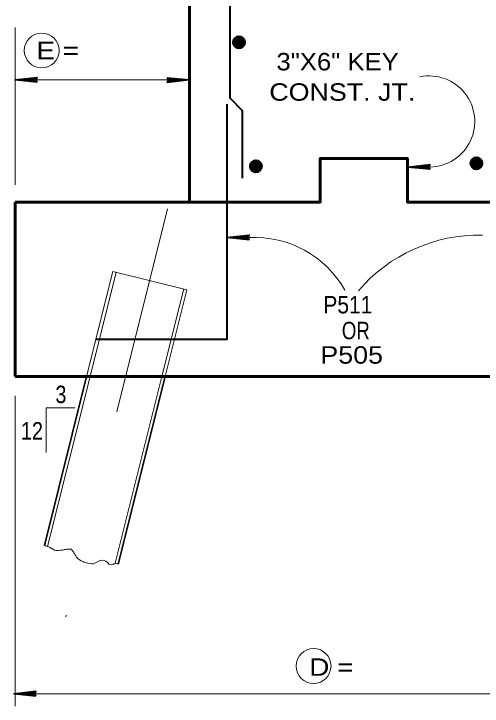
# Model space of a CAD drawing. Extents: x 3.64 to 6.84, y -0.8 to 1.19.
# Drawn here: x 5.0183 to 5.2422, y -0.2994 to 0.0313 of the extents above; entities that cross this region are included whole.
import ezdxf
from ezdxf.enums import TextEntityAlignment as Align

# ---------------------------------------------------------------- set-up
doc = ezdxf.new("R2010")
doc.units = 0
doc.header["$LTSCALE"] = 0.0033
doc.linetypes.add('DOT_DASHED', pattern=[7.7, 5, -1.2, 0.3, -1.2])
doc.linetypes.add('MEDIUM_DASHED', pattern=[4.5, 3, -1.5])
doc.layers.add('1', color=7, linetype='Continuous', lineweight=40)
doc.layers.add('5', color=7, linetype='MEDIUM_DASHED', lineweight=13)

msp = doc.modelspace()

# ---------------------------------------------------------------- linework, layer by layer
at = {"layer": '1', "lineweight": 13}
for p, q in [((5.018917, -0.050417), (5.018917, 0.024667)), ((5.018917, -0.000333), (5.100333, -0.000333)), ((5.018917, -0.151167), (5.018917, -0.299417)), ((5.033833, -0.156917), (5.033833, -0.17825)), ((5.033833, -0.156917), (5.0475, -0.156917)), ((5.018417, -0.2935), (5.35175, -0.2935))]:
    msp.add_line(p, q, dxfattribs=at)
at = {"layer": '1'}
for p, q in [((5.12825, 0.018917), (5.127, 0.020083)), ((5.12375, 0.017), (5.127667, 0.01625)), ((5.12375, 0.016833), (5.127583, 0.016083)), ((5.12375, 0.016583), (5.127583, 0.015917)), ((5.123833, 0.01925), (5.128417, 0.017083)), ((5.123833, 0.017417), (5.12775, 0.016667)), ((5.123917, 0.017833), (5.12775, 0.017083)), ((5.123917, 0.017667), (5.12775, 0.016917)), ((5.124, 0.01825), (5.127833, 0.017583)), ((5.124, 0.018083), (5.127833, 0.017333)), ((5.124083, 0.018833), (5.128, 0.018083)), ((5.124083, 0.018667), (5.128, 0.017917)), ((5.124083, 0.018417), (5.127917, 0.017667)), ((5.124167, 0.01925), (5.128083, 0.018583)), ((5.124167, 0.019083), (5.128083, 0.018333)), ((5.12425, 0.019583), (5.128083, 0.018917)), ((5.126167, 0.01875), (5.1275, 0.01975)), ((5.123667, 0.0165), (5.1275, 0.01575)), ((5.123667, 0.016333), (5.1275, 0.015583)), ((5.128, 0.016083), (5.12425, 0.015667)), ((5.132333, -0.039667), (5.136167, -0.040333)), ((5.13425, -0.0405), (5.135583, -0.0395)), ((5.136333, -0.040333), (5.135083, -0.039167)), ((5.237333, -0.038583), (5.241917, -0.04075)), ((5.2375, -0.039583), (5.241333, -0.04025)), ((5.237583, -0.039), (5.2415, -0.03975)), ((5.237583, -0.039167), (5.2415, -0.039917)), ((5.237583, -0.039417), (5.241417, -0.040167)), ((5.237667, -0.038583), (5.241583, -0.03925)), ((5.237667, -0.03875), (5.241583, -0.0395)), ((5.23775, -0.03825), (5.241583, -0.038917)), ((5.239667, -0.039083), (5.241, -0.038083)), ((5.24175, -0.038917), (5.2405, -0.03775)), ((5.13175, -0.04275), (5.135583, -0.0435)), ((5.13175, -0.042917), (5.135583, -0.043667)), ((5.131833, -0.04225), (5.13575, -0.043)), ((5.131833, -0.042417), (5.135667, -0.043167)), ((5.131833, -0.042667), (5.135667, -0.043333)), ((5.131917, -0.04), (5.1365, -0.042167)), ((5.131917, -0.041833), (5.135833, -0.042583)), ((5.132, -0.041417), (5.135833, -0.042167)), ((5.132, -0.041583), (5.135833, -0.042333)), ((5.132083, -0.041), (5.135917, -0.041667)), ((5.132083, -0.041167), (5.135917, -0.041917)), ((5.132167, -0.040417), (5.136083, -0.041167)), ((5.132167, -0.040583), (5.136083, -0.041333)), ((5.132167, -0.040833), (5.136, -0.041583)), ((5.13225, -0.04), (5.136167, -0.040667)), ((5.13225, -0.040167), (5.136167, -0.040917)), ((5.237167, -0.041333), (5.241, -0.042083)), ((5.237167, -0.0415), (5.241, -0.04225)), ((5.23725, -0.040833), (5.241167, -0.041583)), ((5.23725, -0.041), (5.241083, -0.04175)), ((5.23725, -0.04125), (5.241083, -0.041917)), ((5.237333, -0.040417), (5.24125, -0.041167)), ((5.237417, -0.04), (5.24125, -0.04075)), ((5.237417, -0.040167), (5.24125, -0.040917)), ((5.2375, -0.03975), (5.241333, -0.0405)), ((5.2415, -0.04175), (5.23775, -0.042167)), ((5.136083, -0.043167), (5.132333, -0.043583))]:
    msp.add_line(p, q, dxfattribs=at)
at = {"layer": '1', "lineweight": 60}
for p, q in [((5.128417, 0.017083), (5.123667, 0.016333)), ((5.124083, 0.01925), (5.123917, 0.016333)), ((5.124333, 0.01925), (5.124083, 0.016333)), ((5.1245, 0.01925), (5.124333, 0.01625)), ((5.124667, 0.01925), (5.124417, 0.01625)), ((5.124833, 0.01925), (5.124667, 0.01625)), ((5.125083, 0.01925), (5.124917, 0.01625)), ((5.125333, 0.01925), (5.125083, 0.01625)), ((5.125417, 0.019167), (5.12525, 0.01625)), ((5.125583, 0.019167), (5.125417, 0.01625)), ((5.12575, 0.019167), (5.125583, 0.01625)), ((5.126, 0.019167), (5.12575, 0.01625)), ((5.126167, 0.019167), (5.126, 0.01625)), ((5.126417, 0.019083), (5.126167, 0.016167)), ((5.126667, 0.019083), (5.126417, 0.016167)), ((5.126833, 0.019083), (5.126667, 0.016167)), ((5.126917, 0.019083), (5.12675, 0.016167)), ((5.127083, 0.019083), (5.126917, 0.016167)), ((5.127167, 0.019083), (5.127, 0.016167)), ((5.127417, 0.019), (5.127167, 0.016083)), ((5.127583, 0.019), (5.127417, 0.016083)), ((5.12775, 0.019), (5.1275, 0.016083)), ((5.127917, 0.019), (5.12775, 0.016083)), ((5.128167, 0.019), (5.128, 0.016083)), ((5.128417, 0.017083), (5.12825, 0.018917)), ((5.237583, -0.038583), (5.237417, -0.0415)), ((5.237833, -0.038583), (5.237583, -0.0415)), ((5.238, -0.038583), (5.237833, -0.041583)), ((5.238167, -0.038583), (5.237917, -0.041583)), ((5.238333, -0.038583), (5.238167, -0.041583)), ((5.238583, -0.038583), (5.238417, -0.041583)), ((5.238833, -0.038583), (5.238583, -0.041583)), ((5.238917, -0.038667), (5.23875, -0.041583)), ((5.239083, -0.038667), (5.238917, -0.041583)), ((5.23925, -0.038667), (5.239083, -0.041583)), ((5.2395, -0.038667), (5.23925, -0.041583)), ((5.239667, -0.038667), (5.2395, -0.041583)), ((5.239917, -0.03875), (5.239667, -0.041667)), ((5.240167, -0.03875), (5.239917, -0.041667)), ((5.240333, -0.03875), (5.240167, -0.041667)), ((5.240417, -0.03875), (5.24025, -0.041667)), ((5.240583, -0.03875), (5.240417, -0.041667)), ((5.240667, -0.03875), (5.2405, -0.041667)), ((5.240917, -0.038833), (5.240667, -0.04175)), ((5.241083, -0.038833), (5.240917, -0.04175)), ((5.24125, -0.038833), (5.241, -0.04175)), ((5.241417, -0.038833), (5.24125, -0.04175)), ((5.241667, -0.038833), (5.2415, -0.04175)), ((5.241917, -0.04075), (5.24175, -0.038917)), ((5.1365, -0.042167), (5.13175, -0.042917)), ((5.132167, -0.04), (5.132, -0.042917)), ((5.132417, -0.04), (5.132167, -0.042917)), ((5.132583, -0.04), (5.132417, -0.043)), ((5.13275, -0.04), (5.1325, -0.043)), ((5.132917, -0.04), (5.13275, -0.043)), ((5.133167, -0.04), (5.133, -0.043)), ((5.133417, -0.04), (5.133167, -0.043)), ((5.1335, -0.040083), (5.133333, -0.043)), ((5.133667, -0.040083), (5.1335, -0.043)), ((5.133833, -0.040083), (5.133667, -0.043)), ((5.134083, -0.040083), (5.133833, -0.043)), ((5.13425, -0.040083), (5.134083, -0.043)), ((5.1345, -0.040167), (5.13425, -0.043083)), ((5.13475, -0.040167), (5.1345, -0.043083)), ((5.134917, -0.040167), (5.13475, -0.043083)), ((5.135, -0.040167), (5.134833, -0.043083)), ((5.135167, -0.040167), (5.135, -0.043083)), ((5.13525, -0.040167), (5.135083, -0.043083)), ((5.1355, -0.04025), (5.13525, -0.043167)), ((5.135667, -0.04025), (5.1355, -0.043167)), ((5.135833, -0.04025), (5.135583, -0.043167)), ((5.136, -0.04025), (5.135833, -0.043167)), ((5.13625, -0.04025), (5.136083, -0.043167)), ((5.1365, -0.042167), (5.136333, -0.040333)), ((5.241917, -0.04075), (5.237167, -0.0415)), ((5.018917, -0.142), (5.018917, -0.058667)), ((5.35225, -0.142), (5.018917, -0.142))]:
    msp.add_line(p, q, dxfattribs=at)
at = {"layer": '1', "lineweight": 35}
for p, q in [((5.02925, 0.00075), (5.021917, -0.000083)), ((5.02925, 0.000583), (5.021917, -0.000167)), ((5.02925, 0.0005), (5.021917, -0.000333)), ((5.029333, 0.000333), (5.022, -0.000417)), ((5.091833, 0.000667), (5.099667, -0.00025)), ((5.091833, 0.000667), (5.099667, -0.00025)), ((5.091833, 0.000583), (5.099667, -0.00025)), ((5.091833, 0.0005), (5.099667, -0.000333)), ((5.091833, 0.0005), (5.099667, -0.0005)), ((5.0295, -0.000333), (5.018917, -0.000333)), ((5.02925, -0.001167), (5.021417, -0.000167)), ((5.02925, -0.001167), (5.021417, -0.000333)), ((5.02925, -0.001333), (5.021417, -0.000417)), ((5.02925, -0.001333), (5.021417, -0.000417)), ((5.02925, -0.00125), (5.021417, -0.000417)), ((5.091583, -0.000333), (5.102167, -0.000333)), ((5.09175, -0.001), (5.099083, -0.00025)), ((5.091833, -0.001167), (5.099167, -0.000333)), ((5.091833, -0.00125), (5.099167, -0.0005)), ((5.091833, -0.001417), (5.099167, -0.000583)), ((5.21725, -0.041917), (5.206667, -0.041917)), ((5.217, -0.04275), (5.209167, -0.04175)), ((5.217, -0.04275), (5.209167, -0.041917)), ((5.217, -0.042917), (5.209167, -0.042)), ((5.217, -0.042917), (5.209167, -0.042)), ((5.217, -0.042833), (5.209167, -0.042)), ((5.217, -0.040833), (5.209667, -0.041667)), ((5.217, -0.041), (5.209667, -0.04175)), ((5.217, -0.041083), (5.209667, -0.041917)), ((5.217083, -0.04125), (5.20975, -0.042)), ((5.130833, -0.075583), (5.12025, -0.075583)), ((5.130583, -0.076417), (5.12275, -0.075417)), ((5.130583, -0.076417), (5.12275, -0.075583)), ((5.130583, -0.076583), (5.12275, -0.075667)), ((5.130583, -0.076583), (5.12275, -0.075667)), ((5.130583, -0.0765), (5.12275, -0.075667)), ((5.130583, -0.0745), (5.12325, -0.075333)), ((5.130583, -0.074667), (5.12325, -0.075417)), ((5.130583, -0.07475), (5.12325, -0.075583)), ((5.130667, -0.074917), (5.123333, -0.075667)), ((5.028917, -0.2935), (5.018333, -0.2935)), ((5.028667, -0.294333), (5.020833, -0.293333)), ((5.028667, -0.294333), (5.020833, -0.2935)), ((5.028667, -0.2945), (5.020833, -0.293583)), ((5.028667, -0.2945), (5.020833, -0.293583)), ((5.028667, -0.294417), (5.020833, -0.293583)), ((5.028667, -0.292417), (5.021333, -0.29325)), ((5.028667, -0.292583), (5.021333, -0.293333)), ((5.028667, -0.292667), (5.021333, -0.2935)), ((5.02875, -0.292833), (5.021417, -0.293583))]:
    msp.add_line(p, q, dxfattribs=at)
at = {"layer": '1', "lineweight": 60}
for points in [[(5.018917, -0.058667), (5.10225, -0.058667), (5.10225, 0.274667), (5.268917, 0.274667), (5.268917, -0.058667), (5.35225, -0.058667)], [(5.1275, 0.015583), (5.1275, 0.01975), (5.125833, 0.015083), (5.126333, 0.02025), (5.12425, 0.015667), (5.125, 0.020167), (5.126583, 0.015167), (5.123417, 0.0185), (5.12825, 0.018917), (5.125, 0.01525), (5.127, 0.020083), (5.123833, 0.01925), (5.123667, 0.016333)], [(5.12425, 0.015667), (5.12575, 0.017917), (5.123583, 0.018833), (5.125583, 0.02025), (5.12575, 0.018), (5.127417, 0.015667), (5.123417, 0.018), (5.126167, 0.01875)], [(5.127, 0.020083), (5.12575, 0.017917), (5.128, 0.016083)], [(5.12325, 0.017583), (5.128417, 0.01825), (5.123833, 0.01925)], [(5.10225, -0.058667), (5.16475, -0.058667), (5.16475, -0.037833), (5.206417, -0.037833), (5.206417, -0.058667), (5.268917, -0.058667)], [(5.135583, -0.043667), (5.135583, -0.0395), (5.133917, -0.044167), (5.134417, -0.039), (5.132333, -0.043583), (5.133083, -0.039083), (5.134667, -0.044083), (5.1315, -0.04075), (5.136333, -0.040333), (5.133083, -0.044), (5.135083, -0.039167), (5.131917, -0.04), (5.13175, -0.042917)], [(5.132333, -0.043583), (5.133833, -0.041333), (5.131667, -0.040417), (5.133667, -0.039), (5.133833, -0.04125), (5.1355, -0.043583), (5.1315, -0.04125), (5.13425, -0.0405)], [(5.135083, -0.039167), (5.133833, -0.041333), (5.136083, -0.043167)], [(5.23675, -0.04025), (5.241917, -0.039583), (5.237333, -0.038583)], [(5.241, -0.04225), (5.241, -0.038083), (5.239333, -0.04275), (5.239833, -0.037583), (5.23775, -0.042167), (5.2385, -0.037667), (5.240083, -0.042667), (5.236917, -0.039333), (5.24175, -0.038917), (5.2385, -0.042583), (5.2405, -0.03775), (5.237333, -0.038583), (5.237167, -0.0415)], [(5.23775, -0.042167), (5.23925, -0.039917), (5.237083, -0.039), (5.239083, -0.037583), (5.23925, -0.039833), (5.240917, -0.042167), (5.236917, -0.039833), (5.239667, -0.039083)], [(5.2405, -0.03775), (5.23925, -0.039917), (5.2415, -0.04175)], [(5.131333, -0.041667), (5.1365, -0.041), (5.131917, -0.04)]]:
    msp.add_lwpolyline(points, dxfattribs=at)
at = {"layer": '1'}
for points in [[(5.127417, 0.254), (5.127417, 0.205333), (5.1215, 0.199417), (5.1215, -0.008917), (5.127417, -0.014833), (5.127417, -0.04725)], [(5.123667, 0.016333), (5.12575, 0.015083), (5.1275, 0.015583), (5.128417, 0.017083)], [(5.057833, -0.124083), (5.120333, -0.124083), (5.120333, -0.011917)], [(5.13175, -0.042917), (5.133833, -0.044167), (5.135583, -0.043667), (5.1365, -0.042167)], [(5.237167, -0.0415), (5.23925, -0.04275), (5.241, -0.04225), (5.241917, -0.04075)]]:
    msp.add_lwpolyline(points, dxfattribs=at)
at = {"layer": '1', "lineweight": 35}
for points in [[(5.0295, -0.001417), (5.018917, -0.000333), (5.0295, 0.000833), (5.028917, -0.000333)], [(5.02875, -0.000417), (5.024083, -0.0005), (5.024083, -0.000417), (5.025, -0.000417), (5.02875, -0.0005), (5.02575, -0.000583), (5.028917, -0.000667), (5.026667, -0.00075), (5.028917, -0.000833), (5.025417, -0.000583), (5.02075, -0.000417), (5.021667, -0.000167), (5.020417, -0.000167), (5.02875, -0.000167), (5.026333, 0), (5.028917, 0), (5.023583, -0.000417), (5.028917, 0.00025)], [(5.091583, 0.00075), (5.102167, -0.000333), (5.091583, -0.0015), (5.092167, -0.000333)], [(5.092333, -0.00025), (5.097, -0.000167), (5.097, -0.00025), (5.096083, -0.00025), (5.092333, -0.000167), (5.095333, -0.000083), (5.092167, 0), (5.094417, 0.000083), (5.092167, 0.000167), (5.095667, -0.000083), (5.100333, -0.00025), (5.099417, -0.0005), (5.100667, -0.0005), (5.092333, -0.0005), (5.09475, -0.000667), (5.092167, -0.000667), (5.0975, -0.00025), (5.092167, -0.000917)], [(5.21725, -0.043), (5.206667, -0.041917), (5.21725, -0.04075), (5.216667, -0.041917)], [(5.2165, -0.042), (5.211833, -0.042083), (5.211833, -0.042), (5.21275, -0.042), (5.2165, -0.042083), (5.2135, -0.042167), (5.216667, -0.04225), (5.214417, -0.042333), (5.216667, -0.042417), (5.213167, -0.042167), (5.2085, -0.042), (5.209417, -0.04175), (5.208167, -0.04175), (5.2165, -0.04175), (5.214083, -0.041583), (5.216667, -0.041583), (5.211333, -0.042), (5.216667, -0.041333)], [(5.130833, -0.076667), (5.12025, -0.075583), (5.130833, -0.074417), (5.13025, -0.075583)], [(5.130083, -0.075667), (5.125417, -0.07575), (5.125417, -0.075667), (5.126333, -0.075667), (5.130083, -0.07575), (5.127083, -0.075833), (5.13025, -0.075917), (5.128, -0.076), (5.13025, -0.076083), (5.12675, -0.075833), (5.122083, -0.075667), (5.123, -0.075417), (5.12175, -0.075417), (5.130083, -0.075417), (5.127667, -0.07525), (5.13025, -0.07525), (5.124917, -0.075667), (5.13025, -0.075)], [(5.028917, -0.294583), (5.018333, -0.2935), (5.028917, -0.292333), (5.028333, -0.2935)], [(5.028167, -0.293583), (5.0235, -0.293667), (5.0235, -0.293583), (5.024417, -0.293583), (5.028167, -0.293667), (5.025167, -0.29375), (5.028333, -0.293833), (5.026083, -0.293917), (5.028333, -0.294), (5.024833, -0.29375), (5.020167, -0.293583), (5.021083, -0.293333), (5.019833, -0.293333), (5.028167, -0.293333), (5.02575, -0.293167), (5.028333, -0.293167), (5.023, -0.293583), (5.028333, -0.292917)]]:
    msp.add_lwpolyline(points, close=True, dxfattribs=at)
for points in [[(5.02875, -0.000417), (5.029167, -0.001167), (5.028917, -0.000917), (5.02875, -0.000583), (5.0285, -0.000667), (5.028667, -0.001), (5.028833, -0.00025), (5.029, 0.00025), (5.02925, 0.000667)], [(5.092333, -0.00025), (5.091917, 0.0005), (5.092167, 0.00025), (5.092333, -0.000083), (5.092583, 0), (5.092417, 0.000333), (5.09225, -0.000417), (5.092083, -0.000917), (5.091833, -0.001333)], [(5.2165, -0.042), (5.216917, -0.04275), (5.216667, -0.0425), (5.2165, -0.042167), (5.21625, -0.04225), (5.216417, -0.042583), (5.216583, -0.041833), (5.21675, -0.041333), (5.217, -0.040917)], [(5.130083, -0.075667), (5.1305, -0.076417), (5.13025, -0.076167), (5.130083, -0.075833), (5.129833, -0.075917), (5.13, -0.07625), (5.130167, -0.0755), (5.130333, -0.075), (5.130583, -0.074583)], [(5.028167, -0.293583), (5.028583, -0.294333), (5.028333, -0.294083), (5.028167, -0.29375), (5.027917, -0.293833), (5.028083, -0.294167), (5.02825, -0.293417), (5.028417, -0.292917), (5.028667, -0.2925)]]:
    msp.add_lwpolyline(points, dxfattribs=at)
at = {"layer": '1', "lineweight": 13}
for centre in [(5.031667, 0.01375), (5.161583, -0.28025)]:
    msp.add_circle(centre, 0.008333, dxfattribs=at)
at = {"layer": '1', "lineweight": 60}
for centre in [(5.125917, 0.017683), (5.134, -0.041567), (5.239417, -0.04015)]:
    msp.add_circle(centre, 0.00264, dxfattribs=at)
at = {"layer": '1', "lineweight": 13}
for centre, radius, start, end in [((5.216829, -0.020151), 0.02177, 271.10937, 101.69263), ((5.133284, -0.125296), 0.049773, 29.5481, 92.8223), ((5.240845, -0.150605), 0.076202, 88.94317, 139.38493)]:
    msp.add_arc(centre, radius, start, end, dxfattribs=at)
at = {"layer": '5', "linetype": 'DOT_DASHED'}
msp.add_line((5.091833, -0.061833), (5.043167, -0.256833), dxfattribs=at)
at = {"layer": '5'}
for p, q in [((5.065667, -0.09175), (5.052917, -0.142667)), ((5.06725, -0.092167), (5.054583, -0.142667)), ((5.065667, -0.09175), (5.101, -0.100583)), ((5.0995, -0.100167), (5.088833, -0.142667)), ((5.101, -0.100583), (5.090417, -0.142667))]:
    msp.add_line(p, q, dxfattribs=at)
at = {"layer": '5', "linetype": 'Continuous', "lineweight": 35}
for p, q in [((5.052917, -0.142667), (5.033, -0.22275)), ((5.090417, -0.142667), (5.06825, -0.231583))]:
    msp.add_line(p, q, dxfattribs=at)
at = {"layer": '5', "linetype": 'Continuous'}
for p, q in [((5.054583, -0.142667), (5.0345, -0.223083)), ((5.088833, -0.142667), (5.06675, -0.231167))]:
    msp.add_line(p, q, dxfattribs=at)
msp.add_spline([(5.033, -0.22275), (5.0345, -0.223083), (5.037833, -0.224833), (5.041583, -0.224833), (5.043667, -0.2245), (5.04625, -0.224833), (5.046583, -0.225333), (5.0475, -0.226917), (5.048333, -0.22825), (5.05125, -0.230333), (5.05375, -0.231167), (5.057083, -0.231167), (5.059583, -0.229833), (5.063, -0.230667), (5.06375, -0.231583), (5.065917, -0.231583), (5.06675, -0.231167), (5.06825, -0.231583)], degree=3, dxfattribs=at)

# ---------------------------------------------------------------- texts
at = {"layer": '1'}
for s, height, width, p in [('E =      ', 0.008334, 1.2, (5.029083, 0.009583)), ('3"X6" KEY', 0.008334, 1.1, (5.143833, 0.00425)), ('CONST. JT. ', 0.008334, 1.15, (5.140417, -0.01025)), ('P511', 0.008333, 0.9, (5.16625, -0.111833)), ('OR', 0.008333, 0.8, (5.175083, -0.124167)), ('P505', 0.008333, 1.15, (5.164833, -0.135833)), ('D =      ', 0.008334, 1.2, (5.1595, -0.284917))]:
    msp.add_text(s, height=height, dxfattribs=dict(at, width=width)).set_placement(p)
at = {"layer": '1', "width": 0.85}
msp.add_text('3', height=0.008334, dxfattribs=at).set_placement((5.040833, -0.154667), align=Align.CENTER)
msp.add_text('12', height=0.008334, dxfattribs=at).set_placement((5.03225, -0.172083), align=Align.RIGHT)

doc.saveas('drawing.dxf')
